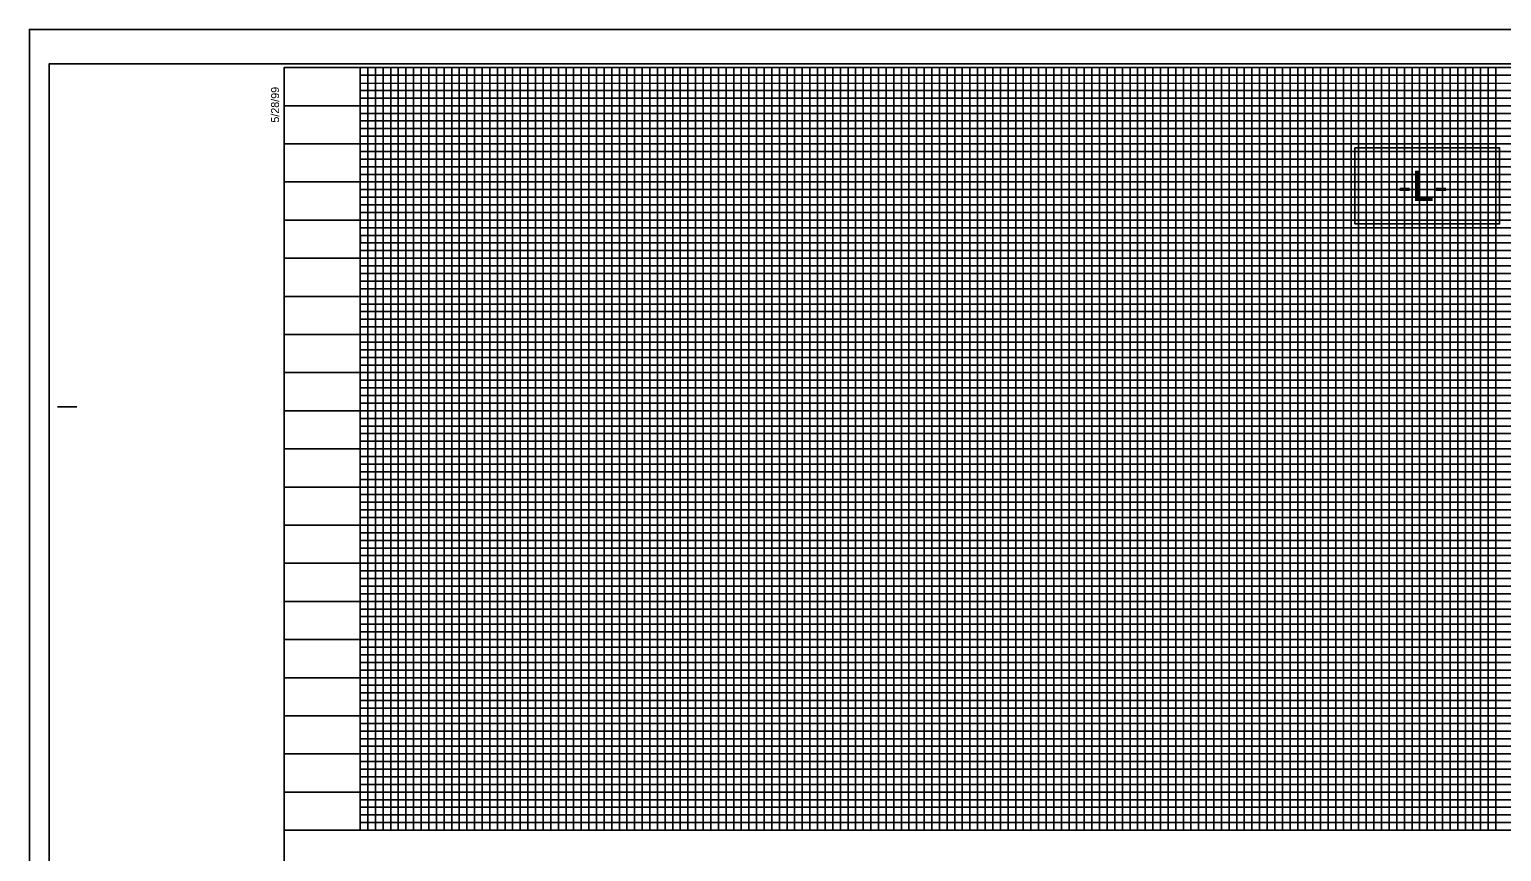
# Model space of a CAD drawing. Extents: x 1648862 to 1650739, y 844691 to 845791.
# Drawn here: x 1648862 to 1649828, y 845252 to 845791 of the extents above; entities that cross this region are included whole.
import ezdxf

# ---------------------------------------------------------------- set-up
doc = ezdxf.new("R2010")
doc.units = 0
for name, color, linetype in [('Prop Conc Barrier Precast Reinforced Single Face', 7, 'Continuous'), ('Prop Conc Barrier Transition Section', 7, 'Continuous'), ('Prop Conc Expressway Gutter', 7, 'Continuous'), ('Prop DGN Element Guardrail', 7, 'Continuous'), ('Prop Dimension', 7, 'Continuous'), ('Prop Dimension Text', 7, 'Continuous'), ('Prop Easement Construction', 7, 'Continuous'), ('Prop Easement Construction Station Offsets', 7, 'Continuous'), ('Prop Easement Permanent Utility Station Offsets', 7, 'Continuous')]:
    doc.layers.add(name, color=color, linetype=linetype)

msp = doc.modelspace()

# ---------------------------------------------------------------- linework, layer by layer
at = {"layer": 'Prop Conc Barrier Transition Section'}
msp.add_lwpolyline([(1648862.28, 844691.02), (1650546.28, 844691.02), (1650546.28, 845791.02), (1648862.28, 845791.02)], close=True, dxfattribs=at)
at = {"layer": 'Prop Conc Expressway Gutter'}
for p, q in [((1649079.28, 845761.02), (1650179.28, 845761.02)), ((1649079.28, 845756.02), (1649079.28, 845756.02)), ((1649079.28, 845756.02), (1649079.28, 845756.02)), ((1650179.28, 845755.98), (1649079.28, 845755.67)), ((1649079.28, 845751.02), (1650179.28, 845751.02)), ((1650329.23, 845631.02), (1649079.28, 845631.02)), ((1650329.28, 845626.02), (1649079.28, 845626.02)), ((1650329.28, 845621.02), (1649079.28, 845621.02)), ((1649079.28, 845611.02), (1650329.28, 845611.02)), ((1650329.28, 845606.02), (1649079.28, 845606.02)), ((1649079.28, 845601.02), (1650479.28, 845601.02)), ((1650479.28, 845581.02), (1649079.28, 845581.02)), ((1649079.28, 845576.02), (1650479.28, 845576.02)), ((1650479.28, 845556.02), (1649079.28, 845556.02)), ((1649079.28, 845551.02), (1650479.28, 845551.02)), ((1650479.28, 845531.02), (1649079.28, 845531.02)), ((1649079.28, 845526.02), (1650479.28, 845526.02)), ((1650479.28, 845521.02), (1649079.28, 845521.02)), ((1649079.28, 845511.02), (1650479.28, 845511.02)), ((1650479.28, 845506.02), (1649079.28, 845506.02)), ((1649079.28, 845501.02), (1650479.28, 845501.02)), ((1650479.28, 845496.02), (1649079.28, 845496.02)), ((1649079.28, 845486.02), (1650479.28, 845486.02)), ((1650479.28, 845481.02), (1649079.28, 845481.02)), ((1649079.28, 845476.02), (1650479.28, 845476.02)), ((1650479.28, 845471.02), (1649079.28, 845471.02)), ((1649079.28, 845461.02), (1650479.28, 845461.02)), ((1650479.28, 845456.02), (1649079.28, 845456.02)), ((1649079.28, 845451.02), (1650479.28, 845451.02)), ((1650479.28, 845446.02), (1649079.28, 845446.02)), ((1649079.28, 845436.02), (1650479.28, 845436.02)), ((1650479.28, 845431.02), (1649079.28, 845431.02)), ((1649079.28, 845426.02), (1650479.28, 845426.02)), ((1650479.28, 845421.02), (1649079.28, 845421.02)), ((1649079.28, 845411.02), (1650479.28, 845411.02)), ((1650479.28, 845406.02), (1649079.28, 845406.02)), ((1649079.28, 845401.02), (1650479.28, 845401.02)), ((1650479.28, 845396.02), (1649079.28, 845396.02)), ((1649079.28, 845386.02), (1650479.28, 845386.02)), ((1650479.28, 845381.02), (1649079.28, 845381.02)), ((1650479.28, 845376.02), (1649079.28, 845376.02)), ((1650479.28, 845371.02), (1649079.28, 845371.02)), ((1649079.28, 845361.02), (1650479.28, 845361.02)), ((1650479.28, 845356.02), (1649079.28, 845356.02)), ((1649079.28, 845351.02), (1650479.28, 845351.02)), ((1650479.28, 845346.02), (1649079.28, 845346.02)), ((1649079.28, 845336.02), (1650479.28, 845336.02)), ((1650479.28, 845331.02), (1649079.28, 845331.02)), ((1649079.28, 845326.02), (1650479.28, 845326.02)), ((1650479.28, 845321.02), (1649079.28, 845321.02)), ((1649079.28, 845311.02), (1650479.28, 845311.02)), ((1650479.28, 845306.02), (1649079.28, 845306.02)), ((1649079.28, 845301.02), (1650479.28, 845301.02)), ((1650479.28, 845296.02), (1649079.28, 845296.02)), ((1649079.28, 845286.02), (1650479.28, 845286.02)), ((1650479.28, 845281.02), (1649079.28, 845281.02)), ((1649079.28, 845276.02), (1650479.28, 845276.02))]:
    msp.add_line(p, q, dxfattribs=at)
for points in [[(1649084.28, 845766.02), (1649084.28, 845266.02), (1649089.28, 845266.02), (1649089.28, 845766.02), (1649094.28, 845766.02), (1649094.28, 845266.02), (1649099.28, 845266.02), (1649099.28, 845766.02), (1649109.28, 845766.02), (1649109.28, 845266.02), (1649114.28, 845266.02), (1649114.28, 845766.02), (1649119.28, 845766.02), (1649119.28, 845266.02), (1649124.28, 845266.02), (1649134.28, 845266.02), (1649139.28, 845266.02), (1649139.28, 845766.02), (1649144.28, 845766.02), (1649144.28, 845266.02), (1649149.28, 845266.02), (1649149.28, 845766.02), (1649159.28, 845766.02), (1649159.28, 845266.02), (1649164.28, 845266.02), (1649164.28, 845766.02), (1649169.28, 845766.02), (1649169.28, 845266.02), (1649174.28, 845266.02), (1649174.28, 845766.02), (1649184.28, 845766.02), (1649184.28, 845266.02), (1649189.28, 845266.02), (1649189.28, 845766.02), (1649194.28, 845766.02), (1649194.28, 845266.02), (1649199.28, 845266.02), (1649199.28, 845766.02), (1649209.28, 845766.02), (1649209.28, 845266.02), (1649214.28, 845266.02), (1649214.28, 845766.02), (1649219.28, 845766.02), (1649219.28, 845266.02), (1649224.28, 845266.02), (1649224.28, 845766.02), (1649234.28, 845766.02), (1649234.28, 845266.02), (1649239.28, 845266.02), (1649239.28, 845766.02), (1649244.28, 845766.02), (1649244.28, 845266.02), (1649249.28, 845266.02), (1649249.28, 845766.02), (1649259.28, 845766.02), (1649259.28, 845266.02), (1649264.28, 845266.02), (1649264.28, 845766.02), (1649269.28, 845766.02), (1649269.28, 845266.02), (1649274.28, 845266.02), (1649274.28, 845766.02), (1649284.28, 845766.02), (1649284.28, 845266.02), (1649289.28, 845266.02), (1649289.28, 845766.02), (1649294.28, 845766.02), (1649294.28, 845266.02)], [(1649124.28, 845266.02), (1649124.28, 845766.02), (1649134.28, 845766.02), (1649134.28, 845266.02)], [(1649294.28, 845266.02), (1649299.28, 845266.02), (1649299.28, 845766.02), (1649309.28, 845766.02), (1649309.28, 845266.02), (1649314.28, 845266.02), (1649314.28, 845766.02), (1649319.28, 845766.02), (1649319.28, 845266.02), (1649324.28, 845266.02), (1649324.28, 845766.02), (1649334.28, 845766.02), (1649334.28, 845266.02), (1649339.28, 845266.02), (1649339.28, 845766.02), (1649344.28, 845766.02), (1649344.28, 845266.02), (1649349.28, 845266.02), (1649349.28, 845766.02), (1649359.28, 845766.02), (1649359.28, 845266.02), (1649364.28, 845266.02), (1649364.28, 845766.02), (1649369.28, 845766.02), (1649369.28, 845266.02), (1649374.28, 845266.02), (1649374.28, 845766.02), (1649384.28, 845766.02), (1649384.28, 845266.02), (1649389.28, 845266.02), (1649389.28, 845766.02), (1649394.28, 845766.02), (1649394.28, 845266.02), (1649399.28, 845266.02), (1649399.28, 845766.02), (1649409.28, 845766.02), (1649409.28, 845266.02), (1649414.28, 845266.02), (1649414.28, 845766.02), (1649419.28, 845766.02), (1649419.28, 845266.02), (1649424.28, 845266.02), (1649424.28, 845766.02), (1649434.28, 845766.02), (1649434.28, 845266.02), (1649439.28, 845266.02), (1649439.28, 845766.02), (1649444.28, 845766.02), (1649444.28, 845266.02), (1649449.28, 845266.02), (1649449.28, 845766.02), (1649459.28, 845766.02), (1649459.28, 845266.02), (1649464.28, 845266.02), (1649464.28, 845766.02), (1649469.28, 845766.02), (1649469.28, 845266.02), (1649474.28, 845266.02), (1649474.28, 845766.02), (1649484.28, 845766.02), (1649484.28, 845266.02), (1649489.28, 845266.02), (1649489.28, 845766.02), (1649494.28, 845766.02), (1649494.28, 845266.02), (1649499.28, 845266.02), (1649499.28, 845766.02), (1649509.28, 845766.02), (1649509.28, 845266.02), (1649514.28, 845266.02), (1649514.28, 845766.02), (1649519.28, 845766.02), (1649519.28, 845266.02), (1649524.28, 845266.02), (1649524.28, 845766.02), (1649534.28, 845766.02), (1649534.28, 845266.02), (1649539.28, 845266.02), (1649539.28, 845766.02), (1649544.28, 845766.02), (1649544.28, 845266.02), (1649549.28, 845266.02), (1649549.28, 845766.02), (1649559.28, 845766.02), (1649559.28, 845266.02), (1649564.28, 845266.02), (1649564.28, 845766.02), (1649569.28, 845766.02), (1649569.28, 845266.02), (1649574.28, 845266.02), (1649574.28, 845766.02), (1649584.28, 845766.02), (1649584.28, 845266.02), (1649589.28, 845266.02), (1649589.28, 845766.02), (1649594.28, 845766.02), (1649594.28, 845266.02), (1649599.28, 845266.02), (1649599.28, 845766.02), (1649609.28, 845766.02)], [(1649609.28, 845766.02), (1649609.28, 845266.02), (1649614.28, 845266.02), (1649614.28, 845766.02), (1649619.28, 845766.02), (1649619.28, 845266.02), (1649624.28, 845266.02), (1649624.28, 845766.02), (1649634.28, 845766.02), (1649634.28, 845266.02), (1649639.28, 845266.02), (1649639.28, 845766.02), (1649644.28, 845766.02), (1649644.28, 845266.02), (1649649.28, 845266.02), (1649649.28, 845766.02), (1649659.28, 845766.02), (1649659.28, 845266.02), (1649664.28, 845266.02), (1649664.28, 845766.02), (1649669.28, 845766.02), (1649669.28, 845266.02), (1649674.28, 845266.02), (1649674.28, 845766.02), (1649684.28, 845766.02), (1649684.28, 845266.02), (1649689.28, 845266.02), (1649689.28, 845766.02), (1649694.28, 845766.02), (1649694.28, 845266.02), (1649699.28, 845266.02), (1649699.28, 845766.02), (1649709.28, 845766.02), (1649709.28, 845266.02), (1649714.28, 845266.02), (1649714.28, 845766.02), (1649719.28, 845766.02), (1649719.28, 845266.02), (1649724.28, 845266.02), (1649724.28, 845766.02), (1649734.28, 845766.02), (1649734.28, 845266.02), (1649734.28, 845266.02), (1649739.28, 845266.02), (1649739.28, 845766.02), (1649744.28, 845766.02), (1649744.28, 845266.02), (1649749.28, 845266.02), (1649749.28, 845766.02), (1649759.28, 845766.02), (1649759.28, 845266.02), (1649764.28, 845266.02), (1649764.28, 845766.02), (1649769.28, 845766.02), (1649769.28, 845266.02), (1649774.28, 845266.02), (1649774.28, 845766.02), (1649784.28, 845766.02), (1649784.28, 845266.02), (1649789.28, 845266.02), (1649789.28, 845766.02), (1649794.28, 845766.02), (1649794.28, 845266.02), (1649799.28, 845266.02), (1649799.28, 845766.02), (1649809.28, 845766.02), (1649809.28, 845266.02), (1649814.28, 845266.02), (1649814.28, 845766.02), (1649819.28, 845766.02), (1649819.28, 845266.02), (1649824.28, 845266.02), (1649824.28, 845766.02), (1649834.28, 845766.02)], [(1650179.28, 845746.02), (1649079.28, 845746.02), (1649079.28, 845736.02), (1650329.28, 845736.02)], [(1650329.23, 845731.02), (1649079.28, 845731.02), (1649079.28, 845726.02), (1650329.28, 845726.02)], [(1650329.28, 845721.02), (1649079.28, 845721.02), (1649079.28, 845711.02), (1650329.28, 845711.02)], [(1650329.28, 845706.02), (1649079.28, 845706.02), (1649079.28, 845701.02), (1650329.28, 845701.02)], [(1650329.28, 845696.02), (1649079.28, 845696.02), (1649079.28, 845686.02), (1650329.28, 845686.02)], [(1650329.28, 845681.02), (1649079.28, 845681.02), (1649079.28, 845676.02), (1650329.28, 845676.02)], [(1650329.28, 845671.02), (1649079.28, 845671.02), (1649079.28, 845661.02), (1650329.28, 845661.02)], [(1650329.28, 845655.92), (1649079.38, 845655.92), (1649079.38, 845651.02), (1650329.28, 845651.02)], [(1650329.28, 845646.02), (1649079.28, 845646.02), (1649079.28, 845636.02), (1650329.28, 845636.02)], [(1650479.28, 845596.02), (1649079.28, 845596.02), (1649079.28, 845586.02), (1650479.28, 845586.02)], [(1650479.28, 845571.02), (1649079.28, 845571.02), (1649079.28, 845561.02), (1650479.28, 845561.02)], [(1650479.28, 845546.02), (1649079.28, 845546.02), (1649079.28, 845536.02), (1650479.28, 845536.02)], [(1650479.28, 845271.02), (1649079.28, 845271.02)]]:
    msp.add_lwpolyline(points, dxfattribs=at)
at = {"layer": 'Prop DGN Element Guardrail'}
for p, q in [((1648880.78, 845543.52), (1648893.28, 845543.52)), ((1649029.28, 845266.02), (1650529.28, 845266.02))]:
    msp.add_line(p, q, dxfattribs=at)
msp.add_lwpolyline([(1650529.28, 845766.02), (1649029.28, 845766.02), (1649029.28, 844716.02), (1650529.28, 844716.02)], close=True, dxfattribs=at)
at = {"layer": 'Prop Dimension'}
for points in [[(1649079.28, 845766.02), (1649079.28, 845266.02), (1649129.28, 845266.02), (1649129.28, 845766.02), (1649179.28, 845766.02), (1649179.28, 845266.02), (1649229.28, 845266.02), (1649229.28, 845766.02), (1649279.28, 845766.02), (1649279.28, 845266.02), (1649329.28, 845266.02), (1649329.28, 845766.02), (1649379.28, 845766.02), (1649379.28, 845266.02), (1649429.28, 845266.02), (1649429.28, 845766.02), (1649479.28, 845766.02), (1649479.28, 845266.02), (1649529.28, 845266.02), (1649529.28, 845766.02), (1649579.28, 845766.02), (1649579.28, 845266.02), (1649629.28, 845266.02), (1649629.28, 845766.02), (1649679.28, 845766.02), (1649679.28, 845266.02), (1649729.28, 845266.02), (1649729.28, 845766.02), (1649779.28, 845766.02), (1649779.28, 845266.02), (1649829.28, 845266.02)], [(1649029.28, 845716.02), (1650329.28, 845716.02)], [(1650329.28, 845666.02), (1649029.28, 845666.02), (1649029.28, 845616.02), (1650329.28, 845616.02)], [(1650529.28, 845566.02), (1649029.28, 845566.02), (1649029.28, 845516.02), (1650529.28, 845516.02)], [(1650529.28, 845466.02), (1649029.28, 845466.02), (1649029.28, 845416.02), (1650529.28, 845416.02)], [(1650529.28, 845366.02), (1649029.28, 845366.02), (1649029.28, 845366.02), (1649029.28, 845316.02), (1650529.28, 845316.02)]]:
    msp.add_lwpolyline(points, dxfattribs=at)
at = {"layer": 'Prop Dimension Text'}
msp.add_line((1649029.28, 845741.02), (1650179.28, 845741.02), dxfattribs=at)
for points in [[(1649104.28, 845766.02), (1649104.28, 845266.02), (1649154.28, 845266.02), (1649154.28, 845766.02), (1649204.28, 845766.02), (1649204.28, 845266.02), (1649254.28, 845266.02), (1649254.28, 845766.02), (1649304.28, 845766.02), (1649304.28, 845266.02), (1649354.28, 845266.02), (1649354.28, 845766.02), (1649404.28, 845766.02), (1649404.28, 845266.02), (1649454.28, 845266.02), (1649454.28, 845766.02), (1649504.28, 845766.02), (1649504.28, 845266.02), (1649554.28, 845266.02), (1649554.28, 845766.02), (1649604.28, 845766.02), (1649604.28, 845266.02), (1649654.28, 845266.02), (1649654.28, 845266.02), (1649654.28, 845766.02), (1649704.28, 845766.02), (1649704.28, 845266.02), (1649754.28, 845266.02), (1649754.28, 845766.02), (1649804.28, 845766.02), (1649804.28, 845266.02), (1649854.28, 845266.02)], [(1650329.28, 845691.02), (1649029.28, 845691.02), (1649029.28, 845641.02), (1650329.28, 845641.02)], [(1650529.28, 845591.02), (1649029.28, 845591.02), (1649029.28, 845541.02), (1650354.28, 845541.02)], [(1650529.28, 845491.02), (1649029.28, 845491.02), (1649029.28, 845441.02), (1650529.28, 845441.02)], [(1650529.28, 845391.02), (1649029.28, 845391.02), (1649029.28, 845341.02), (1650529.28, 845341.02)], [(1650529.28, 845291.02), (1649029.28, 845291.02)]]:
    msp.add_lwpolyline(points, dxfattribs=at)
at = {"layer": 'Prop Easement Construction'}
msp.add_lwpolyline([(1648875.28, 844713.47), (1650541.78, 844713.47), (1650541.78, 845768.57), (1648875.28, 845768.57)], close=True, dxfattribs=at)
at = {"layer": 'Prop Easement Construction Station Offsets'}
for p, q in [((1649079.28, 845266.02), (1649079.28, 845766.02)), ((1649129.28, 845266.02), (1649129.28, 845766.02)), ((1649179.28, 845266.02), (1649179.28, 845766.02)), ((1649229.28, 845266.02), (1649229.28, 845766.02)), ((1649279.28, 845266.02), (1649279.28, 845766.02)), ((1649329.28, 845266.02), (1649329.28, 845766.02)), ((1649379.28, 845266.02), (1649379.28, 845766.02)), ((1649429.28, 845266.02), (1649429.28, 845766.02)), ((1649479.28, 845266.02), (1649479.28, 845766.02)), ((1649529.28, 845266.02), (1649529.28, 845766.02)), ((1649579.28, 845266.02), (1649579.28, 845766.02)), ((1649629.28, 845266.02), (1649629.28, 845766.02)), ((1649679.28, 845266.02), (1649679.28, 845766.02)), ((1649729.28, 845266.02), (1649729.28, 845766.02)), ((1649779.28, 845266.02), (1649779.28, 845766.02)), ((1650329.23, 845716.02), (1649029.28, 845716.02)), ((1650329.23, 845666.02), (1649029.28, 845666.02)), ((1650329.28, 845616.02), (1649029.28, 845616.02)), ((1650529.28, 845566.02), (1649029.28, 845566.02)), ((1650529.28, 845516.02), (1649029.28, 845516.02)), ((1650529.28, 845466.02), (1649029.28, 845466.02)), ((1650529.28, 845416.02), (1649029.28, 845416.02)), ((1650529.28, 845366.02), (1649029.28, 845366.02)), ((1650529.28, 845316.02), (1649029.28, 845316.02))]:
    msp.add_line(p, q, dxfattribs=at)
at = {"layer": 'Prop Easement Permanent Utility Station Offsets'}
msp.add_lwpolyline([(1649731.78, 845713.52), (1649731.78, 845663.52), (1649826.78, 845663.52), (1649826.78, 845713.52)], close=True, dxfattribs=at)

# ---------------------------------------------------------------- texts
at = {"layer": 'Prop Conc Barrier Precast Reinforced Single Face'}
msp.add_text('-L-', height=20, dxfattribs=at).set_placement((1649760.04, 845678.52))
at = {"layer": 'Prop DGN Element Guardrail'}
msp.add_text('5/28/99', height=5.25, rotation=90, dxfattribs=at).set_placement((1649026.04, 845729.94))
msp.add_text('5/28/99', height=5.25, rotation=90, dxfattribs=at).set_placement((1649026.04, 845729.94))

doc.saveas('drawing.dxf')
